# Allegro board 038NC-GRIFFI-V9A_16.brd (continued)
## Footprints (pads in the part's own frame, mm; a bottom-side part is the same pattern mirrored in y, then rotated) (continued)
PG_LTXDX_F_X1_PMVIX_SL07
  round 0.508 hole 3.2 unplated: (-37.184,154.842)
  round 0.051 hole 2.489x2.21 unplated: (-36.185,220.292)
  rect 1.016x1.016 hole 0.559: A1(-41.814,218.796)
  round 1.016 hole 0.559: A2(-42.939,217.796) A3(-41.814,216.796) A4(-42.939,215.796) A5(-41.814,214.796) A6(-42.939,213.796) A7(-41.814,212.796) A8(-42.939,211.796) A9(-41.814,210.796) A10(-42.939,209.796) A11(-41.814,208.796) A12(-42.939,207.796) A13(-41.814,206.796) A14(-42.939,205.796) A15(-41.814,204.796) A16(-42.939,203.796) A17(-41.814,202.796) A18(-42.939,201.796) A19(-41.814,200.796) A20(-42.939,199.796) A21(-41.814,198.796) A22(-42.939,197.796) A23(-41.814,196.796) A24(-42.939,195.796) A25(-41.814,194.796) A26(-42.939,193.796) A27(-41.814,192.796) A28(-42.939,191.796) A29(-41.814,190.796) A30(-42.939,189.796) A31(-41.814,188.796) A32(-42.939,187.796) A33(-41.814,186.796) A34(-42.939,185.796) A35(-41.814,184.796) A36(-42.939,183.796) A37(-41.814,182.796) A38(-42.939,181.796) A39(-41.814,180.796) A40(-42.939,179.796) A41(-41.814,178.796) A42(-42.939,177.796) A43(-41.814,176.796) A44(-42.939,175.796) A45(-41.814,174.796) A46(-42.939,173.796) A47(-41.814,172.796) A48(-42.939,171.796) A49(-41.814,170.796) A50(-42.939,169.796) A51(-41.814,168.796) A52(-42.939,167.796) A53(-41.814,166.796) A54(-42.939,165.796) A55(-41.814,164.796) A56(-42.939,163.796) A57(-41.814,162.796) A58(-42.939,161.796) A59(-41.814,160.796) A60(-42.939,159.796) A61(-41.814,158.796) B1(-39.565,218.796) B2(-40.69,217.796) B3(-39.565,216.796) B4(-40.69,215.796) B5(-39.565,214.796) B6(-40.69,213.796) B7(-39.565,212.796) B8(-40.69,211.796) B9(-39.565,210.796) B10(-40.69,209.796) B11(-39.565,208.796) B12(-40.69,207.796) B13(-39.565,206.796) B14(-40.69,205.796) B15(-39.565,204.796) B16(-40.69,203.796) B17(-39.565,202.796) B18(-40.69,201.796) B19(-39.565,200.796) B20(-40.69,199.796) B21(-39.565,198.796) B22(-40.69,197.796) B23(-39.565,196.796) B24(-40.69,195.796) B25(-39.565,194.796) B26(-40.69,193.796) B27(-39.565,192.796) B28(-40.69,191.796) B29(-39.565,190.796) B30(-40.69,189.796) B31(-39.565,188.796) B32(-40.69,187.796) B33(-39.565,186.796) B34(-40.69,185.796) B35(-39.565,184.796) B36(-40.69,183.796) B37(-39.565,182.796) B38(-40.69,181.796) B39(-39.565,180.796) B40(-40.69,179.796) B41(-39.565,178.796) B42(-40.69,177.796) B43(-39.565,176.796) B44(-40.69,175.796) B45(-39.565,174.796) B46(-40.69,173.796) B47(-39.565,172.796) B48(-40.69,171.796) B49(-39.565,170.796) B50(-40.69,169.796) B51(-39.565,168.796) B52(-40.69,167.796) B53(-39.565,166.796) B54(-40.69,165.796) B55(-39.565,164.796) B56(-40.69,163.796) B57(-39.565,162.796) B58(-40.69,161.796) B59(-39.565,160.796) B60(-40.69,159.796) B61(-39.565,158.796) B62(-40.69,157.796) C1(-37.314,218.796) C2(-38.44,217.796) C3(-37.314,216.796) C4(-38.44,215.796) C5(-37.314,214.796) C6(-38.44,213.796) C7(-37.314,212.796) C8(-38.44,211.796) C9(-37.314,210.796) C10(-38.44,209.796) C11(-37.314,208.796) C12(-38.44,207.796) C13(-37.314,206.796) C14(-38.44,205.796) C15(-37.314,204.796) C16(-38.44,203.796) C17(-37.314,202.796) C18(-38.44,201.796) C19(-37.314,200.796) C20(-38.44,199.796) C21(-37.314,198.796) C22(-38.44,197.796) C23(-37.314,196.796) C24(-38.44,195.796) C25(-37.314,194.796) C26(-38.44,193.796) C27(-37.314,192.796) C28(-38.44,191.796) C29(-37.314,190.796) C30(-38.44,189.796) C31(-37.314,188.796) C32(-38.44,187.796) C33(-37.314,186.796) C34(-38.44,185.796) C35(-37.314,184.796) C36(-38.44,183.796) C37(-37.314,182.796) C38(-38.44,181.796) C39(-37.314,180.796) C40(-38.44,179.796) C41(-37.314,178.796) C42(-38.44,177.796) C43(-37.314,176.796) C44(-38.44,175.796) C45(-37.314,174.796) C46(-38.44,173.796) C47(-37.314,172.796) C48(-38.44,171.796) C49(-37.314,170.796) C50(-38.44,169.796) C51(-37.314,168.796) C52(-38.44,167.796) C53(-37.314,166.796) C54(-38.44,165.796) C55(-37.314,164.796) C56(-38.44,163.796) C57(-37.314,162.796) C58(-38.44,161.796) C59(-37.314,160.796) C60(-38.44,159.796) C61(-37.314,158.796) C62(-38.44,157.796) D1(-35.064,218.796) D2(-36.189,217.796) D3(-35.064,216.796) D4(-36.189,215.796) D5(-35.064,214.796) D6(-36.189,213.796) D7(-35.064,212.796) D8(-36.189,211.796) D9(-35.064,210.796) D10(-36.189,209.796) D11(-35.064,208.796) D12(-36.189,207.796) D13(-35.064,206.796) D14(-36.189,205.796) D15(-35.064,204.796) D16(-36.189,203.796) D17(-35.064,202.796) D18(-36.189,201.796) D19(-35.064,200.796) D20(-36.189,199.796) D21(-35.064,198.796) D22(-36.189,197.796) D23(-35.064,196.796) D24(-36.189,195.796) D25(-35.064,194.796) D26(-36.189,193.796) D27(-35.064,192.796) D28(-36.189,191.796) D29(-35.064,190.796) D30(-36.189,189.796) D31(-35.064,188.796) D32(-36.189,187.796) D33(-35.064,186.796) D34(-36.189,185.796) D35(-35.064,184.796) D36(-36.189,183.796) D37(-35.064,182.796) D38(-36.189,181.796) D39(-35.064,180.796) D40(-36.189,179.796) D41(-35.064,178.796) D42(-36.189,177.796) D43(-35.064,176.796) D44(-36.189,175.796) D45(-35.064,174.796) D46(-36.189,173.796) D47(-35.064,172.796) D48(-36.189,171.796) D49(-35.064,170.796) D50(-36.189,169.796) D51(-35.064,168.796) D52(-36.189,167.796) D53(-35.064,166.796) D54(-36.189,165.796) D55(-35.064,164.796) D56(-36.189,163.796) D57(-35.064,162.796) D58(-36.189,161.796) D59(-35.064,160.796) D60(-36.189,159.796) D61(-35.064,158.796) E1(-32.815,218.796) E2(-33.939,217.796) E3(-32.815,216.796) E4(-33.939,215.796) E5(-32.815,214.796) E6(-33.939,213.796) E7(-32.815,212.796) E8(-33.939,211.796) E9(-32.815,210.796) E10(-33.939,209.796) E11(-32.815,208.796) E12(-33.939,207.796) E13(-32.815,206.796) E14(-33.939,205.796) E15(-32.815,204.796) E16(-33.939,203.796) E17(-32.815,202.796) E18(-33.939,201.796) E19(-32.815,200.796) E20(-33.939,199.796) E21(-32.815,198.796) E22(-33.939,197.796) E23(-32.815,196.796) E24(-33.939,195.796) E25(-32.815,194.796) E26(-33.939,193.796) E27(-32.815,192.796) E28(-33.939,191.796) E29(-32.815,190.796) E30(-33.939,189.796) E31(-32.815,188.796) E32(-33.939,187.796) E33(-32.815,186.796) E34(-33.939,185.796) E35(-32.815,184.796) E36(-33.939,183.796) E37(-32.815,182.796) E38(-33.939,181.796) E39(-32.815,180.796) E40(-33.939,179.796) E41(-32.815,178.796) E42(-33.939,177.796) E43(-32.815,176.796) E44(-33.939,175.796) E45(-32.815,174.796) E46(-33.939,173.796) E47(-32.815,172.796) E48(-33.939,171.796) E49(-32.815,170.796) E50(-33.939,169.796) E51(-32.815,168.796) E52(-33.939,167.796) E53(-32.815,166.796) E54(-33.939,165.796) E55(-32.815,164.796) E56(-33.939,163.796) E57(-32.815,162.796) E58(-33.939,161.796) E59(-32.815,160.796) E60(-33.939,159.796) E61(-32.815,158.796) E62(-33.939,157.796) F1(-30.565,218.796) F2(-31.69,217.796) F3(-30.565,216.796) F4(-31.69,215.796) F5(-30.565,214.796) F6(-31.69,213.796) F7(-30.565,212.796) F8(-31.69,211.796) F9(-30.565,210.796) F10(-31.69,209.796) F11(-30.565,208.796) F12(-31.69,207.796) F13(-30.565,206.796) F14(-31.69,205.796) F15(-30.565,204.796) F16(-31.69,203.796) F17(-30.565,202.796) F18(-31.69,201.796) F19(-30.565,200.796) F20(-31.69,199.796) F21(-30.565,198.796) F22(-31.69,197.796) F23(-30.565,196.796) F24(-31.69,195.796) F25(-30.565,194.796) F26(-31.69,193.796) F27(-30.565,192.796) F28(-31.69,191.796) F29(-30.565,190.796) F30(-31.69,189.796) F31(-30.565,188.796) F32(-31.69,187.796) F33(-30.565,186.796) F34(-31.69,185.796) F35(-30.565,184.796) F36(-31.69,183.796) F37(-30.565,182.796) F38(-31.69,181.796) F39(-30.565,180.796) F40(-31.69,179.796) F41(-30.565,178.796) F42(-31.69,177.796) F43(-30.565,176.796) F44(-31.69,175.796) F45(-30.565,174.796) F46(-31.69,173.796) F47(-30.565,172.796) F48(-31.69,171.796) F49(-30.565,170.796) F50(-31.69,169.796) F51(-30.565,168.796) F52(-31.69,167.796) F53(-30.565,166.796) F54(-31.69,165.796) F55(-30.565,164.796) F56(-31.69,163.796) F57(-30.565,162.796) F58(-31.69,161.796) F59(-30.565,160.796) F60(-31.69,159.796) F61(-30.565,158.796) F62(-31.69,157.796) G2(-29.44,217.796) G4(-29.44,215.796) G6(-29.44,213.796) G8(-29.44,211.796) G10(-29.44,209.796) G12(-29.44,207.796) G14(-29.44,205.796) G16(-29.44,203.796) G18(-29.44,201.796) G20(-29.44,199.796) G22(-29.44,197.796) G24(-29.44,195.796) G26(-29.44,193.796) G28(-29.44,191.796) G30(-29.44,189.796) G32(-29.44,187.796) G34(-29.44,185.796) G36(-29.44,183.796) G38(-29.44,181.796) G40(-29.44,179.796) G42(-29.44,177.796) G44(-29.44,175.796) G46(-29.44,173.796) G48(-29.44,171.796) G50(-29.44,169.796) G52(-29.44,167.796) G54(-29.44,165.796) G56(-29.44,163.796) G58(-29.44,161.796) G60(-29.44,159.796)
  custom 0.257x0.257 smd: Z5(-44.064,214.796) Z7(-44.064,212.796) Z9(-44.064,210.796) Z11(-44.064,208.796) Z13(-44.064,206.796) Z15(-44.064,204.796) Z17(-44.064,202.796) Z19(-44.064,200.796) Z21(-44.064,198.796) Z23(-44.064,196.796) Z25(-44.064,194.796) Z27(-44.064,192.796) Z29(-44.064,190.796) Z31(-44.064,188.796) Z33(-44.064,186.796) Z35(-44.064,184.796) Z37(-44.064,182.796) Z39(-44.064,180.796) Z41(-44.064,178.796) Z43(-44.064,176.796) Z45(-44.064,174.796) Z47(-44.064,172.796) Z49(-44.064,170.796) Z51(-44.064,168.796) Z53(-44.064,166.796) Z55(-44.064,164.796) Z57(-44.064,162.796) Z59(-44.064,160.796) Z61(-44.064,158.796)
PG_LTXDX_F_X1_PMVIX_SL08
  round 0.051 hole 2.489x2.21 unplated: (-12.075,-220.292)
  round 0.508 hole 3.2 unplated: (-11.076,-154.842)
  rect 1.016x1.016 hole 0.559: A1(-6.446,-218.796)
  round 1.016 hole 0.559: A2(-5.321,-217.796) A3(-6.446,-216.796) A4(-5.321,-215.796) A5(-6.446,-214.796) A6(-5.321,-213.796) A7(-6.446,-212.796) A8(-5.321,-211.796) A9(-6.446,-210.796) A10(-5.321,-209.796) A11(-6.446,-208.796) A12(-5.321,-207.796) A13(-6.446,-206.796) A14(-5.321,-205.796) A15(-6.446,-204.796) A16(-5.321,-203.796) A17(-6.446,-202.796) A18(-5.321,-201.796) A19(-6.446,-200.796) A20(-5.321,-199.796) A21(-6.446,-198.796) A22(-5.321,-197.796) A23(-6.446,-196.796) A24(-5.321,-195.796) A25(-6.446,-194.796) A26(-5.321,-193.796) A27(-6.446,-192.796) A28(-5.321,-191.796) A29(-6.446,-190.796) A30(-5.321,-189.796) A31(-6.446,-188.796) A32(-5.321,-187.796) A33(-6.446,-186.796) A34(-5.321,-185.796) A35(-6.446,-184.796) A36(-5.321,-183.796) A37(-6.446,-182.796) A38(-5.321,-181.796) A39(-6.446,-180.796) A40(-5.321,-179.796) A41(-6.446,-178.796) A42(-5.321,-177.796) A43(-6.446,-176.796) A44(-5.321,-175.796) A45(-6.446,-174.796) A46(-5.321,-173.796) A47(-6.446,-172.796) A48(-5.321,-171.796) A49(-6.446,-170.796) A50(-5.321,-169.796) A51(-6.446,-168.796) A52(-5.321,-167.796) A53(-6.446,-166.796) A54(-5.321,-165.796) A55(-6.446,-164.796) A56(-5.321,-163.796) A57(-6.446,-162.796) A58(-5.321,-161.796) A59(-6.446,-160.796) A60(-5.321,-159.796) A61(-6.446,-158.796) B1(-8.695,-218.796) B2(-7.57,-217.796) B3(-8.695,-216.796) B4(-7.57,-215.796) B5(-8.695,-214.796) B6(-7.57,-213.796) B7(-8.695,-212.796) B8(-7.57,-211.796) B9(-8.695,-210.796) B10(-7.57,-209.796) B11(-8.695,-208.796) B12(-7.57,-207.796) B13(-8.695,-206.796) B14(-7.57,-205.796) B15(-8.695,-204.796) B16(-7.57,-203.796) B17(-8.695,-202.796) B18(-7.57,-201.796) B19(-8.695,-200.796) B20(-7.57,-199.796) B21(-8.695,-198.796) B22(-7.57,-197.796) B23(-8.695,-196.796) B24(-7.57,-195.796) B25(-8.695,-194.796) B26(-7.57,-193.796) B27(-8.695,-192.796) B28(-7.57,-191.796) B29(-8.695,-190.796) B30(-7.57,-189.796) B31(-8.695,-188.796) B32(-7.57,-187.796) B33(-8.695,-186.796) B34(-7.57,-185.796) B35(-8.695,-184.796) B36(-7.57,-183.796) B37(-8.695,-182.796) B38(-7.57,-181.796) B39(-8.695,-180.796) B40(-7.57,-179.796) B41(-8.695,-178.796) B42(-7.57,-177.796) B43(-8.695,-176.796) B44(-7.57,-175.796) B45(-8.695,-174.796) B46(-7.57,-173.796) B47(-8.695,-172.796) B48(-7.57,-171.796) B49(-8.695,-170.796) B50(-7.57,-169.796) B51(-8.695,-168.796) B52(-7.57,-167.796) B53(-8.695,-166.796) B54(-7.57,-165.796) B55(-8.695,-164.796) B56(-7.57,-163.796) B57(-8.695,-162.796) B58(-7.57,-161.796) B59(-8.695,-160.796) B60(-7.57,-159.796) B61(-8.695,-158.796) B62(-7.57,-157.796) C1(-10.946,-218.796) C2(-9.82,-217.796) C3(-10.946,-216.796) C4(-9.82,-215.796) C5(-10.946,-214.796) C6(-9.82,-213.796) C7(-10.946,-212.796) C8(-9.82,-211.796) C9(-10.946,-210.796) C10(-9.82,-209.796) C11(-10.946,-208.796) C12(-9.82,-207.796) C13(-10.946,-206.796) C14(-9.82,-205.796) C15(-10.946,-204.796) C16(-9.82,-203.796) C17(-10.946,-202.796) C18(-9.82,-201.796) C19(-10.946,-200.796) C20(-9.82,-199.796) C21(-10.946,-198.796) C22(-9.82,-197.796) C23(-10.946,-196.796) C24(-9.82,-195.796) C25(-10.946,-194.796) C26(-9.82,-193.796) C27(-10.946,-192.796) C28(-9.82,-191.796) C29(-10.946,-190.796) C30(-9.82,-189.796) C31(-10.946,-188.796) C32(-9.82,-187.796) C33(-10.946,-186.796) C34(-9.82,-185.796) C35(-10.946,-184.796) C36(-9.82,-183.796) C37(-10.946,-182.796) C38(-9.82,-181.796) C39(-10.946,-180.796) C40(-9.82,-179.796) C41(-10.946,-178.796) C42(-9.82,-177.796) C43(-10.946,-176.796) C44(-9.82,-175.796) C45(-10.946,-174.796) C46(-9.82,-173.796) C47(-10.946,-172.796) C48(-9.82,-171.796) C49(-10.946,-170.796) C50(-9.82,-169.796) C51(-10.946,-168.796) C52(-9.82,-167.796) C53(-10.946,-166.796) C54(-9.82,-165.796) C55(-10.946,-164.796) C56(-9.82,-163.796) C57(-10.946,-162.796) C58(-9.82,-161.796) C59(-10.946,-160.796) C60(-9.82,-159.796) C61(-10.946,-158.796) C62(-9.82,-157.796) D1(-13.196,-218.796) D2(-12.071,-217.796) D3(-13.196,-216.796) D4(-12.071,-215.796) D5(-13.196,-214.796) D6(-12.071,-213.796) D7(-13.196,-212.796) D8(-12.071,-211.796) D9(-13.196,-210.796) D10(-12.071,-209.796) D11(-13.196,-208.796) D12(-12.071,-207.796) D13(-13.196,-206.796) D14(-12.071,-205.796) D15(-13.196,-204.796) D16(-12.071,-203.796) D17(-13.196,-202.796) D18(-12.071,-201.796) D19(-13.196,-200.796) D20(-12.071,-199.796) D21(-13.196,-198.796) D22(-12.071,-197.796) D23(-13.196,-196.796) D24(-12.071,-195.796) D25(-13.196,-194.796) D26(-12.071,-193.796) D27(-13.196,-192.796) D28(-12.071,-191.796) D29(-13.196,-190.796) D30(-12.071,-189.796) D31(-13.196,-188.796) D32(-12.071,-187.796) D33(-13.196,-186.796) D34(-12.071,-185.796) D35(-13.196,-184.796) D36(-12.071,-183.796) D37(-13.196,-182.796) D38(-12.071,-181.796) D39(-13.196,-180.796) D40(-12.071,-179.796) D41(-13.196,-178.796) D42(-12.071,-177.796) D43(-13.196,-176.796) D44(-12.071,-175.796) D45(-13.196,-174.796) D46(-12.071,-173.796) D47(-13.196,-172.796) D48(-12.071,-171.796) D49(-13.196,-170.796) D50(-12.071,-169.796) D51(-13.196,-168.796) D52(-12.071,-167.796) D53(-13.196,-166.796) D54(-12.071,-165.796) D55(-13.196,-164.796) D56(-12.071,-163.796) D57(-13.196,-162.796) D58(-12.071,-161.796) D59(-13.196,-160.796) D60(-12.071,-159.796) D61(-13.196,-158.796) E1(-15.445,-218.796) E2(-14.321,-217.796) E3(-15.445,-216.796) E4(-14.321,-215.796) E5(-15.445,-214.796) E6(-14.321,-213.796) E7(-15.445,-212.796) E8(-14.321,-211.796) E9(-15.445,-210.796) E10(-14.321,-209.796) E11(-15.445,-208.796) E12(-14.321,-207.796) E13(-15.445,-206.796) E14(-14.321,-205.796) E15(-15.445,-204.796) E16(-14.321,-203.796) E17(-15.445,-202.796) E18(-14.321,-201.796) E19(-15.445,-200.796) E20(-14.321,-199.796) E21(-15.445,-198.796) E22(-14.321,-197.796) E23(-15.445,-196.796) E24(-14.321,-195.796) E25(-15.445,-194.796) E26(-14.321,-193.796) E27(-15.445,-192.796) E28(-14.321,-191.796) E29(-15.445,-190.796) E30(-14.321,-189.796) E31(-15.445,-188.796) E32(-14.321,-187.796) E33(-15.445,-186.796) E34(-14.321,-185.796) E35(-15.445,-184.796) E36(-14.321,-183.796) E37(-15.445,-182.796) E38(-14.321,-181.796) E39(-15.445,-180.796) E40(-14.321,-179.796) E41(-15.445,-178.796) E42(-14.321,-177.796) E43(-15.445,-176.796) E44(-14.321,-175.796) E45(-15.445,-174.796) E46(-14.321,-173.796) E47(-15.445,-172.796) E48(-14.321,-171.796) E49(-15.445,-170.796) E50(-14.321,-169.796) E51(-15.445,-168.796) E52(-14.321,-167.796) E53(-15.445,-166.796) E54(-14.321,-165.796) E55(-15.445,-164.796) E56(-14.321,-163.796) E57(-15.445,-162.796) E58(-14.321,-161.796) E59(-15.445,-160.796) E60(-14.321,-159.796) E61(-15.445,-158.796) E62(-14.321,-157.796) F1(-17.695,-218.796) F2(-16.57,-217.796) F3(-17.695,-216.796) F4(-16.57,-215.796) F5(-17.695,-214.796) F6(-16.57,-213.796) F7(-17.695,-212.796) F8(-16.57,-211.796) F9(-17.695,-210.796) F10(-16.57,-209.796) F11(-17.695,-208.796) F12(-16.57,-207.796) F13(-17.695,-206.796) F14(-16.57,-205.796) F15(-17.695,-204.796) F16(-16.57,-203.796) F17(-17.695,-202.796) F18(-16.57,-201.796) F19(-17.695,-200.796) F20(-16.57,-199.796) F21(-17.695,-198.796) F22(-16.57,-197.796) F23(-17.695,-196.796) F24(-16.57,-195.796) F25(-17.695,-194.796) F26(-16.57,-193.796) F27(-17.695,-192.796) F28(-16.57,-191.796) F29(-17.695,-190.796) F30(-16.57,-189.796) F31(-17.695,-188.796) F32(-16.57,-187.796) F33(-17.695,-186.796) F34(-16.57,-185.796) F35(-17.695,-184.796) F36(-16.57,-183.796) F37(-17.695,-182.796) F38(-16.57,-181.796) F39(-17.695,-180.796) F40(-16.57,-179.796) F41(-17.695,-178.796) F42(-16.57,-177.796) F43(-17.695,-176.796) F44(-16.57,-175.796) F45(-17.695,-174.796) F46(-16.57,-173.796) F47(-17.695,-172.796) F48(-16.57,-171.796) F49(-17.695,-170.796) F50(-16.57,-169.796) F51(-17.695,-168.796) F52(-16.57,-167.796) F53(-17.695,-166.796) F54(-16.57,-165.796) F55(-17.695,-164.796) F56(-16.57,-163.796) F57(-17.695,-162.796) F58(-16.57,-161.796) F59(-17.695,-160.796) F60(-16.57,-159.796) F61(-17.695,-158.796) F62(-16.57,-157.796) G2(-18.82,-217.796) G4(-18.82,-215.796) G6(-18.82,-213.796) G8(-18.82,-211.796) G10(-18.82,-209.796) G12(-18.82,-207.796) G14(-18.82,-205.796) G16(-18.82,-203.796) G18(-18.82,-201.796) G20(-18.82,-199.796) G22(-18.82,-197.796) G24(-18.82,-195.796) G26(-18.82,-193.796) G28(-18.82,-191.796) G30(-18.82,-189.796) G32(-18.82,-187.796) G34(-18.82,-185.796) G36(-18.82,-183.796) G38(-18.82,-181.796) G40(-18.82,-179.796) G42(-18.82,-177.796) G44(-18.82,-175.796) G46(-18.82,-173.796) G48(-18.82,-171.796) G50(-18.82,-169.796) G52(-18.82,-167.796) G54(-18.82,-165.796) G56(-18.82,-163.796) G58(-18.82,-161.796) G60(-18.82,-159.796)
  custom 0.257x0.257 smd: Z5(-4.196,-214.796) Z7(-4.196,-212.796) Z9(-4.196,-210.796) Z11(-4.196,-208.796) Z13(-4.196,-206.796) Z15(-4.196,-204.796) Z17(-4.196,-202.796) Z19(-4.196,-200.796) Z21(-4.196,-198.796) Z23(-4.196,-196.796) Z25(-4.196,-194.796) Z27(-4.196,-192.796) Z29(-4.196,-190.796) Z31(-4.196,-188.796) Z33(-4.196,-186.796) Z35(-4.196,-184.796) Z37(-4.196,-182.796) Z39(-4.196,-180.796) Z41(-4.196,-178.796) Z43(-4.196,-176.796) Z45(-4.196,-174.796) Z47(-4.196,-172.796) Z49(-4.196,-170.796) Z51(-4.196,-168.796) Z53(-4.196,-166.796) Z55(-4.196,-164.796) Z57(-4.196,-162.796) Z59(-4.196,-160.796) Z61(-4.196,-158.796)
PG_LTXDX_F_X1_PMVIX_SL09
  round 0.508 hole 3.2 unplated: (-13.054,154.842)
  round 0.051 hole 2.489x2.21 unplated: (-12.055,220.292)
  rect 1.016x1.016 hole 0.559: A1(-17.684,218.796)
  round 1.016 hole 0.559: A2(-18.809,217.796) A3(-17.684,216.796) A4(-18.809,215.796) A5(-17.684,214.796) A6(-18.809,213.796) A7(-17.684,212.796) A8(-18.809,211.796) A9(-17.684,210.796) A10(-18.809,209.796) A11(-17.684,208.796) A12(-18.809,207.796) A13(-17.684,206.796) A14(-18.809,205.796) A15(-17.684,204.796) A16(-18.809,203.796) A17(-17.684,202.796) A18(-18.809,201.796) A19(-17.684,200.796) A20(-18.809,199.796) A21(-17.684,198.796) A22(-18.809,197.796) A23(-17.684,196.796) A24(-18.809,195.796) A25(-17.684,194.796) A26(-18.809,193.796) A27(-17.684,192.796) A28(-18.809,191.796) A29(-17.684,190.796) A30(-18.809,189.796) A31(-17.684,188.796) A32(-18.809,187.796) A33(-17.684,186.796) A34(-18.809,185.796) A35(-17.684,184.796) A36(-18.809,183.796) A37(-17.684,182.796) A38(-18.809,181.796) A39(-17.684,180.796) A40(-18.809,179.796) A41(-17.684,178.796) A42(-18.809,177.796) A43(-17.684,176.796) A44(-18.809,175.796) A45(-17.684,174.796) A46(-18.809,173.796) A47(-17.684,172.796) A48(-18.809,171.796) A49(-17.684,170.796) A50(-18.809,169.796) A51(-17.684,168.796) A52(-18.809,167.796) A53(-17.684,166.796) A54(-18.809,165.796) A55(-17.684,164.796) A56(-18.809,163.796) A57(-17.684,162.796) A58(-18.809,161.796) A59(-17.684,160.796) A60(-18.809,159.796) A61(-17.684,158.796) B1(-15.435,218.796) B2(-16.56,217.796) B3(-15.435,216.796) B4(-16.56,215.796) B5(-15.435,214.796) B6(-16.56,213.796) B7(-15.435,212.796) B8(-16.56,211.796) B9(-15.435,210.796) B10(-16.56,209.796) B11(-15.435,208.796) B12(-16.56,207.796) B13(-15.435,206.796) B14(-16.56,205.796) B15(-15.435,204.796) B16(-16.56,203.796) B17(-15.435,202.796) B18(-16.56,201.796) B19(-15.435,200.796) B20(-16.56,199.796) B21(-15.435,198.796) B22(-16.56,197.796) B23(-15.435,196.796) B24(-16.56,195.796) B25(-15.435,194.796) B26(-16.56,193.796) B27(-15.435,192.796) B28(-16.56,191.796) B29(-15.435,190.796) B30(-16.56,189.796) B31(-15.435,188.796) B32(-16.56,187.796) B33(-15.435,186.796) B34(-16.56,185.796) B35(-15.435,184.796) B36(-16.56,183.796) B37(-15.435,182.796) B38(-16.56,181.796) B39(-15.435,180.796) B40(-16.56,179.796) B41(-15.435,178.796) B42(-16.56,177.796) B43(-15.435,176.796) B44(-16.56,175.796) B45(-15.435,174.796) B46(-16.56,173.796) B47(-15.435,172.796) B48(-16.56,171.796) B49(-15.435,170.796) B50(-16.56,169.796) B51(-15.435,168.796) B52(-16.56,167.796) B53(-15.435,166.796) B54(-16.56,165.796) B55(-15.435,164.796) B56(-16.56,163.796) B57(-15.435,162.796) B58(-16.56,161.796) B59(-15.435,160.796) B60(-16.56,159.796) B61(-15.435,158.796) B62(-16.56,157.796) C1(-13.184,218.796) C2(-14.31,217.796) C3(-13.184,216.796) C4(-14.31,215.796) C5(-13.184,214.796) C6(-14.31,213.796) C7(-13.184,212.796) C8(-14.31,211.796) C9(-13.184,210.796) C10(-14.31,209.796) C11(-13.184,208.796) C12(-14.31,207.796) C13(-13.184,206.796) C14(-14.31,205.796) C15(-13.184,204.796) C16(-14.31,203.796) C17(-13.184,202.796) C18(-14.31,201.796) C19(-13.184,200.796) C20(-14.31,199.796) C21(-13.184,198.796) C22(-14.31,197.796) C23(-13.184,196.796) C24(-14.31,195.796) C25(-13.184,194.796) C26(-14.31,193.796) C27(-13.184,192.796) C28(-14.31,191.796) C29(-13.184,190.796) C30(-14.31,189.796) C31(-13.184,188.796) C32(-14.31,187.796) C33(-13.184,186.796) C34(-14.31,185.796) C35(-13.184,184.796) C36(-14.31,183.796) C37(-13.184,182.796) C38(-14.31,181.796) C39(-13.184,180.796) C40(-14.31,179.796) C41(-13.184,178.796) C42(-14.31,177.796) C43(-13.184,176.796) C44(-14.31,175.796) C45(-13.184,174.796) C46(-14.31,173.796) C47(-13.184,172.796) C48(-14.31,171.796) C49(-13.184,170.796) C50(-14.31,169.796) C51(-13.184,168.796) C52(-14.31,167.796) C53(-13.184,166.796) C54(-14.31,165.796) C55(-13.184,164.796) C56(-14.31,163.796) C57(-13.184,162.796) C58(-14.31,161.796) C59(-13.184,160.796) C60(-14.31,159.796) C61(-13.184,158.796) C62(-14.31,157.796) D1(-10.934,218.796) D2(-12.059,217.796) D3(-10.934,216.796) D4(-12.059,215.796) D5(-10.934,214.796) D6(-12.059,213.796) D7(-10.934,212.796) D8(-12.059,211.796) D9(-10.934,210.796) D10(-12.059,209.796) D11(-10.934,208.796) D12(-12.059,207.796) D13(-10.934,206.796) D14(-12.059,205.796) D15(-10.934,204.796) D16(-12.059,203.796) D17(-10.934,202.796) D18(-12.059,201.796) D19(-10.934,200.796) D20(-12.059,199.796) D21(-10.934,198.796) D22(-12.059,197.796) D23(-10.934,196.796) D24(-12.059,195.796) D25(-10.934,194.796) D26(-12.059,193.796) D27(-10.934,192.796) D28(-12.059,191.796) D29(-10.934,190.796) D30(-12.059,189.796) D31(-10.934,188.796) D32(-12.059,187.796) D33(-10.934,186.796) D34(-12.059,185.796) D35(-10.934,184.796) D36(-12.059,183.796) D37(-10.934,182.796) D38(-12.059,181.796) D39(-10.934,180.796) D40(-12.059,179.796) D41(-10.934,178.796) D42(-12.059,177.796) D43(-10.934,176.796) D44(-12.059,175.796) D45(-10.934,174.796) D46(-12.059,173.796) D47(-10.934,172.796) D48(-12.059,171.796) D49(-10.934,170.796) D50(-12.059,169.796) D51(-10.934,168.796) D52(-12.059,167.796) D53(-10.934,166.796) D54(-12.059,165.796) D55(-10.934,164.796) D56(-12.059,163.796) D57(-10.934,162.796) D58(-12.059,161.796) D59(-10.934,160.796) D60(-12.059,159.796) D61(-10.934,158.796) E1(-8.685,218.796) E2(-9.809,217.796) E3(-8.685,216.796) E4(-9.809,215.796) E5(-8.685,214.796) E6(-9.809,213.796) E7(-8.685,212.796) E8(-9.809,211.796) E9(-8.685,210.796) E10(-9.809,209.796) E11(-8.685,208.796) E12(-9.809,207.796) E13(-8.685,206.796) E14(-9.809,205.796) E15(-8.685,204.796) E16(-9.809,203.796) E17(-8.685,202.796) E18(-9.809,201.796) E19(-8.685,200.796) E20(-9.809,199.796) E21(-8.685,198.796) E22(-9.809,197.796) E23(-8.685,196.796) E24(-9.809,195.796) E25(-8.685,194.796) E26(-9.809,193.796) E27(-8.685,192.796) E28(-9.809,191.796) E29(-8.685,190.796) E30(-9.809,189.796) E31(-8.685,188.796) E32(-9.809,187.796) E33(-8.685,186.796) E34(-9.809,185.796) E35(-8.685,184.796) E36(-9.809,183.796) E37(-8.685,182.796) E38(-9.809,181.796) E39(-8.685,180.796) E40(-9.809,179.796) E41(-8.685,178.796) E42(-9.809,177.796) E43(-8.685,176.796) E44(-9.809,175.796) E45(-8.685,174.796) E46(-9.809,173.796) E47(-8.685,172.796) E48(-9.809,171.796) E49(-8.685,170.796) E50(-9.809,169.796) E51(-8.685,168.796) E52(-9.809,167.796) E53(-8.685,166.796) E54(-9.809,165.796) E55(-8.685,164.796) E56(-9.809,163.796) E57(-8.685,162.796) E58(-9.809,161.796) E59(-8.685,160.796) E60(-9.809,159.796) E61(-8.685,158.796) E62(-9.809,157.796) F1(-6.435,218.796) F2(-7.56,217.796) F3(-6.435,216.796) F4(-7.56,215.796) F5(-6.435,214.796) F6(-7.56,213.796) F7(-6.435,212.796) F8(-7.56,211.796) F9(-6.435,210.796) F10(-7.56,209.796) F11(-6.435,208.796) F12(-7.56,207.796) F13(-6.435,206.796) F14(-7.56,205.796) F15(-6.435,204.796) F16(-7.56,203.796) F17(-6.435,202.796) F18(-7.56,201.796) F19(-6.435,200.796) F20(-7.56,199.796) F21(-6.435,198.796) F22(-7.56,197.796) F23(-6.435,196.796) F24(-7.56,195.796) F25(-6.435,194.796) F26(-7.56,193.796) F27(-6.435,192.796) F28(-7.56,191.796) F29(-6.435,190.796) F30(-7.56,189.796) F31(-6.435,188.796) F32(-7.56,187.796) F33(-6.435,186.796) F34(-7.56,185.796) F35(-6.435,184.796) F36(-7.56,183.796) F37(-6.435,182.796) F38(-7.56,181.796) F39(-6.435,180.796) F40(-7.56,179.796) F41(-6.435,178.796) F42(-7.56,177.796) F43(-6.435,176.796) F44(-7.56,175.796) F45(-6.435,174.796) F46(-7.56,173.796) F47(-6.435,172.796) F48(-7.56,171.796) F49(-6.435,170.796) F50(-7.56,169.796) F51(-6.435,168.796) F52(-7.56,167.796) F53(-6.435,166.796) F54(-7.56,165.796) F55(-6.435,164.796) F56(-7.56,163.796) F57(-6.435,162.796) F58(-7.56,161.796) F59(-6.435,160.796) F60(-7.56,159.796) F61(-6.435,158.796) F62(-7.56,157.796) G2(-5.31,217.796) G4(-5.31,215.796) G6(-5.31,213.796) G8(-5.31,211.796) G10(-5.31,209.796) G12(-5.31,207.796) G14(-5.31,205.796) G16(-5.31,203.796) G18(-5.31,201.796) G20(-5.31,199.796) G22(-5.31,197.796) G24(-5.31,195.796) G26(-5.31,193.796) G28(-5.31,191.796) G30(-5.31,189.796) G32(-5.31,187.796) G34(-5.31,185.796) G36(-5.31,183.796) G38(-5.31,181.796) G40(-5.31,179.796) G42(-5.31,177.796) G44(-5.31,175.796) G46(-5.31,173.796) G48(-5.31,171.796) G50(-5.31,169.796) G52(-5.31,167.796) G54(-5.31,165.796) G56(-5.31,163.796) G58(-5.31,161.796) G60(-5.31,159.796)
  custom 0.257x0.257 smd: Z5(-19.934,214.796) Z7(-19.934,212.796) Z9(-19.934,210.796) Z11(-19.934,208.796) Z13(-19.934,206.796) Z15(-19.934,204.796) Z17(-19.934,202.796) Z19(-19.934,200.796) Z21(-19.934,198.796) Z23(-19.934,196.796) Z25(-19.934,194.796) Z27(-19.934,192.796) Z29(-19.934,190.796) Z31(-19.934,188.796) Z33(-19.934,186.796) Z35(-19.934,184.796) Z37(-19.934,182.796) Z39(-19.934,180.796) Z41(-19.934,178.796) Z43(-19.934,176.796) Z45(-19.934,174.796) Z47(-19.934,172.796) Z49(-19.934,170.796) Z51(-19.934,168.796) Z53(-19.934,166.796) Z55(-19.934,164.796) Z57(-19.934,162.796) Z59(-19.934,160.796) Z61(-19.934,158.796)
PG_LTXDX_F_X1_SDU2_SL00_V3
  round 0.051 hole 2.489x2.21 unplated: (-108.595,-220.342)
  round 0.508 hole 3.2 unplated: (-107.596,-154.842)
  rect 1.016x1.016 hole 0.559: A1(-102.966,-218.796)
  round 1.016 hole 0.559: A2(-101.841,-217.796) A3(-102.966,-216.796) A4(-101.841,-215.796) A5(-102.966,-214.796) A6(-101.841,-213.796) A7(-102.966,-212.796) A8(-101.841,-211.796) A9(-102.966,-210.796) A10(-101.841,-209.796) A11(-102.966,-208.796) A12(-101.841,-207.796) A13(-102.966,-206.796) A14(-101.841,-205.796) A15(-102.966,-204.796) A16(-101.841,-203.796) A17(-102.966,-202.796) A18(-101.841,-201.796) A19(-102.966,-200.796) A20(-101.841,-199.796) A21(-102.966,-198.796) A22(-101.841,-197.796) A23(-102.966,-196.796) A24(-101.841,-195.796) A25(-102.966,-194.796) A26(-101.841,-193.796) A27(-102.966,-192.796) A28(-101.841,-191.796) A29(-102.966,-190.796) A30(-101.841,-189.796) A31(-102.966,-188.796) A32(-101.841,-187.796) A33(-102.966,-186.796) A34(-101.841,-185.796) A35(-102.966,-184.796) A36(-101.841,-183.796) A37(-102.966,-182.796) A38(-101.841,-181.796) A39(-102.966,-180.796) A40(-101.841,-179.796) A41(-102.966,-178.796) A42(-101.841,-177.796) A43(-102.966,-176.796) A44(-101.841,-175.796) A45(-102.966,-174.796) A46(-101.841,-173.796) A47(-102.966,-172.796) A48(-101.841,-171.796) A49(-102.966,-170.796) A50(-101.841,-169.796) A51(-102.966,-168.796) A52(-101.841,-167.796) A53(-102.966,-166.796) A54(-101.841,-165.796) A55(-102.966,-164.796) A56(-101.841,-163.796) A57(-102.966,-162.796) A58(-101.841,-161.796) A59(-102.966,-160.796) A60(-101.841,-159.796) A61(-102.966,-158.796) B1(-105.215,-218.796) B2(-104.09,-217.796) B3(-105.215,-216.796) B4(-104.09,-215.796) B5(-105.215,-214.796) B6(-104.09,-213.796) B7(-105.215,-212.796) B8(-104.09,-211.796) B9(-105.215,-210.796) B10(-104.09,-209.796) B11(-105.215,-208.796) B12(-104.09,-207.796) B13(-105.215,-206.796) B14(-104.09,-205.796) B15(-105.215,-204.796) B16(-104.09,-203.796) B17(-105.215,-202.796) B18(-104.09,-201.796) B19(-105.215,-200.796) B20(-104.09,-199.796) B21(-105.215,-198.796) B22(-104.09,-197.796) B23(-105.215,-196.796) B24(-104.09,-195.796) B25(-105.215,-194.796) B26(-104.09,-193.796) B27(-105.215,-192.796) B28(-104.09,-191.796) B29(-105.215,-190.796) B30(-104.09,-189.796) B31(-105.215,-188.796) B32(-104.09,-187.796) B33(-105.215,-186.796) B34(-104.09,-185.796) B35(-105.215,-184.796) B36(-104.09,-183.796) B37(-105.215,-182.796) B38(-104.09,-181.796) B39(-105.215,-180.796) B40(-104.09,-179.796) B41(-105.215,-178.796) B42(-104.09,-177.796) B43(-105.215,-176.796) B44(-104.09,-175.796) B45(-105.215,-174.796) B46(-104.09,-173.796) B47(-105.215,-172.796) B48(-104.09,-171.796) B49(-105.215,-170.796) B50(-104.09,-169.796) B51(-105.215,-168.796) B52(-104.09,-167.796) B53(-105.215,-166.796) B54(-104.09,-165.796) B55(-105.215,-164.796) B56(-104.09,-163.796) B57(-105.215,-162.796) B58(-104.09,-161.796) B59(-105.215,-160.796) B60(-104.09,-159.796) B61(-105.215,-158.796) B62(-104.09,-157.796) C1(-107.466,-218.796) C2(-106.34,-217.796) C3(-107.466,-216.796) C4(-106.34,-215.796) C5(-107.466,-214.796) C6(-106.34,-213.796) C7(-107.466,-212.796) C8(-106.34,-211.796) C9(-107.466,-210.796) C10(-106.34,-209.796) C11(-107.466,-208.796) C12(-106.34,-207.796) C13(-107.466,-206.796) C14(-106.34,-205.796) C15(-107.466,-204.796) C16(-106.34,-203.796) C17(-107.466,-202.796) C18(-106.34,-201.796) C19(-107.466,-200.796) C20(-106.34,-199.796) C21(-107.466,-198.796) C22(-106.34,-197.796) C23(-107.466,-196.796) C24(-106.34,-195.796) C25(-107.466,-194.796) C26(-106.34,-193.796) C27(-107.466,-192.796) C28(-106.34,-191.796) C29(-107.466,-190.796) C30(-106.34,-189.796) C31(-107.466,-188.796) C32(-106.34,-187.796) C33(-107.466,-186.796) C34(-106.34,-185.796) C35(-107.466,-184.796) C36(-106.34,-183.796) C37(-107.466,-182.796) C38(-106.34,-181.796) C39(-107.466,-180.796) C40(-106.34,-179.796) C41(-107.466,-178.796) C42(-106.34,-177.796) C43(-107.466,-176.796) C44(-106.34,-175.796) C45(-107.466,-174.796) C46(-106.34,-173.796) C47(-107.466,-172.796) C48(-106.34,-171.796) C49(-107.466,-170.796) C50(-106.34,-169.796) C51(-107.466,-168.796) C52(-106.34,-167.796) C53(-107.466,-166.796) C54(-106.34,-165.796) C55(-107.466,-164.796) C56(-106.34,-163.796) C57(-107.466,-162.796) C58(-106.34,-161.796) C59(-107.466,-160.796) C60(-106.34,-159.796) C61(-107.466,-158.796) C62(-106.34,-157.796) D1(-109.716,-218.796) D2(-108.591,-217.796) D3(-109.716,-216.796) D4(-108.591,-215.796) D5(-109.716,-214.796) D6(-108.591,-213.796) D7(-109.716,-212.796) D8(-108.591,-211.796) D9(-109.716,-210.796) D10(-108.591,-209.796) D11(-109.716,-208.796) D12(-108.591,-207.796) D13(-109.716,-206.796) D14(-108.591,-205.796) D15(-109.716,-204.796) D16(-108.591,-203.796) D17(-109.716,-202.796) D18(-108.591,-201.796) D19(-109.716,-200.796) D20(-108.591,-199.796) D21(-109.716,-198.796) D22(-108.591,-197.796) D23(-109.716,-196.796) D24(-108.591,-195.796) D25(-109.716,-194.796) D26(-108.591,-193.796) D27(-109.716,-192.796) D28(-108.591,-191.796) D29(-109.716,-190.796) D30(-108.591,-189.796) D31(-109.716,-188.796) D32(-108.591,-187.796) D33(-109.716,-186.796) D34(-108.591,-185.796) D35(-109.716,-184.796) D36(-108.591,-183.796) D37(-109.716,-182.796) D38(-108.591,-181.796) D39(-109.716,-180.796) D40(-108.591,-179.796) D41(-109.716,-178.796) D42(-108.591,-177.796) D43(-109.716,-176.796) D44(-108.591,-175.796) D45(-109.716,-174.796) D46(-108.591,-173.796) D47(-109.716,-172.796) D48(-108.591,-171.796) D49(-109.716,-170.796) D50(-108.591,-169.796) D51(-109.716,-168.796) D52(-108.591,-167.796) D53(-109.716,-166.796) D54(-108.591,-165.796) D55(-109.716,-164.796) D56(-108.591,-163.796) D57(-109.716,-162.796) D58(-108.591,-161.796) D59(-109.716,-160.796) D60(-108.591,-159.796) D61(-109.716,-158.796) E1(-111.965,-218.796) E2(-110.841,-217.796) E3(-111.965,-216.796) E4(-110.841,-215.796) E5(-111.965,-214.796) E6(-110.841,-213.796) E7(-111.965,-212.796) E8(-110.841,-211.796) E9(-111.965,-210.796) E10(-110.841,-209.796) E11(-111.965,-208.796) E12(-110.841,-207.796) E13(-111.965,-206.796) E14(-110.841,-205.796) E15(-111.965,-204.796) E16(-110.841,-203.796) E17(-111.965,-202.796) E18(-110.841,-201.796) E19(-111.965,-200.796) E20(-110.841,-199.796) E21(-111.965,-198.796) E22(-110.841,-197.796) E23(-111.965,-196.796) E24(-110.841,-195.796) E25(-111.965,-194.796) E26(-110.841,-193.796) E27(-111.965,-192.796) E28(-110.841,-191.796) E29(-111.965,-190.796) E30(-110.841,-189.796) E31(-111.965,-188.796) E32(-110.841,-187.796) E33(-111.965,-186.796) E34(-110.841,-185.796) E35(-111.965,-184.796) E36(-110.841,-183.796) E37(-111.965,-182.796) E38(-110.841,-181.796) E39(-111.965,-180.796) E40(-110.841,-179.796) E41(-111.965,-178.796) E42(-110.841,-177.796) E43(-111.965,-176.796) E44(-110.841,-175.796) E45(-111.965,-174.796) E46(-110.841,-173.796) E47(-111.965,-172.796) E48(-110.841,-171.796) E49(-111.965,-170.796) E50(-110.841,-169.796) E51(-111.965,-168.796) E52(-110.841,-167.796) E53(-111.965,-166.796) E54(-110.841,-165.796) E55(-111.965,-164.796) E56(-110.841,-163.796) E57(-111.965,-162.796) E58(-110.841,-161.796) E59(-111.965,-160.796) E60(-110.841,-159.796) E61(-111.965,-158.796) E62(-110.841,-157.796) F1(-114.215,-218.796) F2(-113.09,-217.796) F3(-114.215,-216.796) F4(-113.09,-215.796) F5(-114.215,-214.796) F6(-113.09,-213.796) F7(-114.215,-212.796) F8(-113.09,-211.796) F9(-114.215,-210.796) F10(-113.09,-209.796) F11(-114.215,-208.796) F12(-113.09,-207.796) F13(-114.215,-206.796) F14(-113.09,-205.796) F15(-114.215,-204.796) F16(-113.09,-203.796) F17(-114.215,-202.796) F18(-113.09,-201.796) F19(-114.215,-200.796) F20(-113.09,-199.796) F21(-114.215,-198.796) F22(-113.09,-197.796) F23(-114.215,-196.796) F24(-113.09,-195.796) F25(-114.215,-194.796) F26(-113.09,-193.796) F27(-114.215,-192.796) F28(-113.09,-191.796) F29(-114.215,-190.796) F30(-113.09,-189.796) F31(-114.215,-188.796) F32(-113.09,-187.796) F33(-114.215,-186.796) F34(-113.09,-185.796) F35(-114.215,-184.796) F36(-113.09,-183.796) F37(-114.215,-182.796) F38(-113.09,-181.796) F39(-114.215,-180.796) F40(-113.09,-179.796) F41(-114.215,-178.796) F42(-113.09,-177.796) F43(-114.215,-176.796) F44(-113.09,-175.796) F45(-114.215,-174.796) F46(-113.09,-173.796) F47(-114.215,-172.796) F48(-113.09,-171.796) F49(-114.215,-170.796) F50(-113.09,-169.796) F51(-114.215,-168.796) F52(-113.09,-167.796) F53(-114.215,-166.796) F54(-113.09,-165.796) F55(-114.215,-164.796) F56(-113.09,-163.796) F57(-114.215,-162.796) F58(-113.09,-161.796) F59(-114.215,-160.796) F60(-113.09,-159.796) F61(-114.215,-158.796) F62(-113.09,-157.796) G2(-115.34,-217.796) G4(-115.34,-215.796) G6(-115.34,-213.796) G8(-115.34,-211.796) G10(-115.34,-209.796) G12(-115.34,-207.796) G14(-115.34,-205.796) G16(-115.34,-203.796) G18(-115.34,-201.796) G20(-115.34,-199.796) G22(-115.34,-197.796) G24(-115.34,-195.796) G26(-115.34,-193.796) G28(-115.34,-191.796) G30(-115.34,-189.796) G32(-115.34,-187.796) G34(-115.34,-185.796) G36(-115.34,-183.796) G38(-115.34,-181.796) G40(-115.34,-179.796) G42(-115.34,-177.796) G44(-115.34,-175.796) G46(-115.34,-173.796) G48(-115.34,-171.796) G50(-115.34,-169.796) G52(-115.34,-167.796) G54(-115.34,-165.796) G56(-115.34,-163.796) G58(-115.34,-161.796) G60(-115.34,-159.796)
  custom 0.257x0.257 smd: Z5(-100.716,-214.796) Z7(-100.716,-212.796) Z9(-100.716,-210.796) Z11(-100.716,-208.796) Z13(-100.716,-206.796) Z15(-100.716,-204.796) Z17(-100.716,-202.796) Z19(-100.716,-200.796) Z21(-100.716,-198.796) Z23(-100.716,-196.796) Z25(-100.716,-194.796) Z27(-100.716,-192.796) Z29(-100.716,-190.796) Z31(-100.716,-188.796) Z33(-100.716,-186.796) Z35(-100.716,-184.796) Z37(-100.716,-182.796) Z39(-100.716,-180.796) Z41(-100.716,-178.796) Z43(-100.716,-176.796) Z45(-100.716,-174.796) Z47(-100.716,-172.796) Z49(-100.716,-170.796) Z51(-100.716,-168.796) Z53(-100.716,-166.796) Z55(-100.716,-164.796) Z57(-100.716,-162.796) Z59(-100.716,-160.796) Z61(-100.716,-158.796)
R0201
  rect 0.305x0.356 smd: 1(-0.3,0) 2(0.3,0)
R0402
  custom 0.15x0.15 smd: 1(-0.5,0) 2(0.5,0)
R0603
  rect 0.889x0.889 smd: 1(-0.85,0) 2(0.85,0)
RL_NECUA2_12V_V2
  rect 1.626x1.626 hole 1.041: 1(3.6,1.6)
  round 1.626 hole 1.041: 2(0.4,1.6) 3(-1.8,1.6) 4(-4,1.6) 5(-4,-1.6) 6(-1.8,-1.6) 7(0.4,-1.6) 8(3.6,-1.6)
SK_QFN4X4_56P_0P4MM_GRIFFI
  round 0.508 hole 1.53 unplated: (-8.25,8.25) (8.25,-8.25)
  custom 0.675x0.675 smd: EPAD1(0,0)
  custom 0.338x0.338 smd: EPAD2(0,0)
  rect 0.28x0.25 smd: F1(-2.025,1.2) F2(-2.025,0.8) F3(-1.625,0.4) F4(-2.025,0) F5(-2.025,-0.4) F6(-2.025,-0.8) F7(-2.025,-1.2) F8(-1.2,-2.025) F9(-0.8,-2.025) F10(-0.4,-2.025) F11(0,-2.025) F12(0.4,-2.025) F13(0.8,-2.025) F14(1.2,-2.025) F15(2.025,-1.2) F16(2.025,-0.8) F17(2.025,-0.4) F18(2.025,0) F19(2.025,0.4) F20(2.025,0.8) F21(2.025,1.2) F22(1.2,2.025) F23(0.8,2.025) F24(0.4,1.625) F25(0,2.025) F26(-0.4,2.025) F27(-0.8,2.025) F28(-1.2,2.025) S1(-1.625,1.2) S2(-1.625,0.8) S3(-2.025,0.4) S4(-1.625,0) S5(-1.625,-0.4) S6(-1.625,-0.8) S7(-1.625,-1.2) S8(-1.2,-1.625) S9(-0.8,-1.625) S10(-0.4,-1.625) S11(0,-1.625) S12(0.4,-1.625) S13(0.8,-1.625) S14(1.2,-1.625) S15(1.625,-1.2) S16(1.625,-0.8) S17(1.625,-0.4) S18(1.625,0) S19(1.625,0.4) S20(1.625,0.8) S21(1.625,1.2) S22(1.2,1.625) S23(0.8,1.625) S24(0.4,2.025) S25(0,1.625) S26(-0.4,1.625) S27(-0.8,1.625) S28(-1.2,1.625)
  round 0.61 hole 0.307: G1(-1,1) G2(0,1) G3(1,1) G4(-1,0) G5(-1,-1) G6(1,-1)
  round 6.096 hole 3.759: NUT1(-11,11) NUT2(11,11) NUT3(-11,-11) NUT4(11,-11)
SO8_195X127MM
  rect 1.778x0.508 smd: 1(-2.477,1.905) 2(-2.477,0.635) 3(-2.477,-0.635) 4(-2.477,-1.905) 5(2.477,-1.905) 6(2.477,-0.635) 7(2.477,0.635) 8(2.477,1.905)
SO8_206X127MM
  rect 1.905x1.143 smd: 1(-2.616,2.095) 4(-2.616,-2.095) 5(2.616,-2.095) 8(2.616,2.095)
  rect 1.905x0.762 smd: 2(-2.616,0.635) 3(-2.616,-0.635) 6(2.616,-0.635) 7(2.616,0.635)
SOCKET_CODE
  round 0.051 smd: 1(0,0)
TO263_3
  rect 1.27x3.302 smd: 1(-2.54,-6.35) 2(0,-6.35) 3(2.54,-6.35)
  rect 10.414x11.43 smd: 4(0,2.413)
TP_040_T
  round 1.016 smd: 1(0,0)
TSOT23-5
  rect 0.635x1.27 smd: 1(0.95,1.31) 2(0,1.31) 3(-0.95,1.31) 4(-0.95,-1.31) 5(0.95,-1.31)
unnamed#2
  round 1.016 smd: 1(0,0)

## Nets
48V: SLOT0.F2 SLOT0.G2
48V_RTN: SLOT0.D2 SLOT0.E2
+15V: BC10.1 BC11.1 FUSE1.1 SLOT0.B8 SLOT0.C8 SLOT0.D8 T_+15V.1(TP)
-15V: BC12.2 BC13.2 SLOT0.E8 SLOT0.F8 SLOT0.G8 T_-15V.1(TP)
